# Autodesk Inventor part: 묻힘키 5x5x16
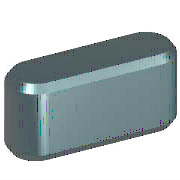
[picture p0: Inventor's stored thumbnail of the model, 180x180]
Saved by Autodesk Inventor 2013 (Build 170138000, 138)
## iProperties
IsCustomPart: 1
Created: 2012-02
Part Number: 묻힘키 5x5x16
Material: 강철, 연강
Description: 평행 키
Document SubType Name: Modeling
Standard: JIS B 1301
Designer: mdu-01
Standards Organization: JIS
Language: ko-KR
Size Designation: 5x5x16
Categories: <MemberInstance><Categories><Category DisplayName="샤프트 부품" InternalName="7f7aeb1f-a693-4053-b835-cee3144e0d98" Mnemonic="SHFT"><Category DisplayName="키" Interna
Density: 1 g/cm^3
Author: mdu-01
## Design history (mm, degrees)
workplane "Work Plane1"
workplane "Work Plane2"
sketch "스케치1"
  geometry: L1 (2.5, 2.5)-(13.5, 2.5); L2 (13.5, -2.5)-(2.5, -2.5); L3 (0, 9.4)-(0, -7.4) reference; L4 (-5, 0)-(30, 0) reference; L5 (16, 0)-(16, 7); A1 r 2.5 centre (2.5, 0) between (2.5, 2.5) and (2.5, -2.5); A2 r 2.5 centre (13.5, 0) between (13.5, -2.5) and (13.5, 2.5)
  constraints: 6 end point, 5 point on circle, 4 tangent, 3 point on line, 2 centre point, 1 horizontal, 1 parallel, 1 perpendicular
  dimensions: "d0" = 2.5 radius of A1 (= 0.5 x PB); "d13" = 2.5 radius of A2 (= 0.5 x PB); "d14" = 16 distance between parallel lines of L5 L3 (= NLG)
extrude "본체1" new body sketch "스케치1" taper "d3" = 0 deg; stored distance "d4" = 10
workplane "Work Plane3"
body "Solid1"
chamfer "모따기1" distance "d8" = 0.4 (= PHH); stored, may be unused: second distance "d9" = 0.4 (= PHH), angle "d15" = 45 deg
other parameters: "d1" = -3 (= -PNT), "d2" = 2 (= PH - PNT), "NLG" = 16 [user parameter; used in 3 equation terms], "PB" = 5 [user parameter; used in 2 equation terms], "PNT" = 3 [user parameter; used in 2 equation terms], "PH" = 5 [user parameter; used in 1 equation term], "PHH" = 0.4 [user parameter; used in 2 equation terms], "d10" = 0, "d16" = 0, "d17" = 0, "d18" = 0, "WDMIN" = 12 [user parameter], "PLB2" = 16 (= NLG) [user parameter], "WDMAX" = 17 [user parameter], "PLB1" = 16 (= NLG) [user parameter], "RR" = 0.16 [user parameter], "PUEB" = 2.3 [user parameter]
